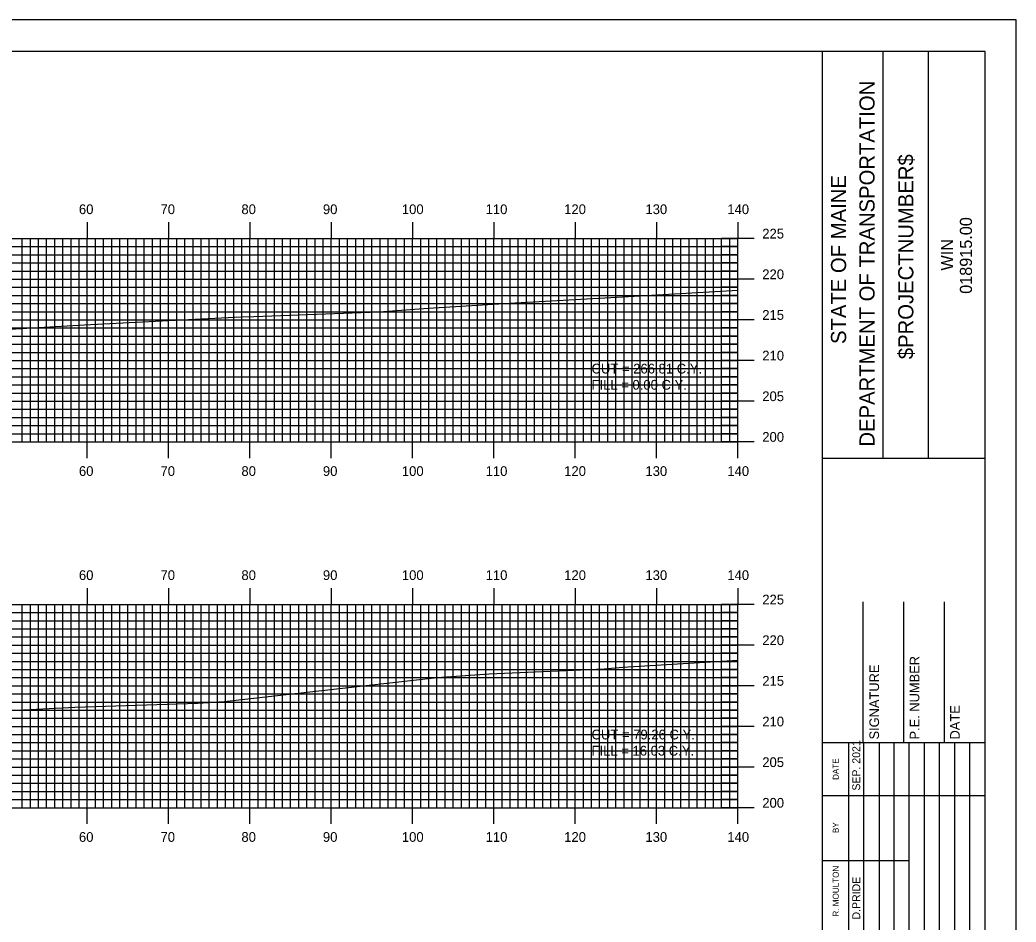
# Model space of a CAD drawing. Extents: x 853316 to 853659, y 364785 to 365005.
# Drawn here: x 853533.5 to 853656, y 364894.2 to 365005.1 of the extents above; entities that cross this region are included whole.
import ezdxf

# ---------------------------------------------------------------- set-up
doc = ezdxf.new("R2010")
doc.units = 0
for name, color, linetype in [('BORDER', 7, 'Continuous'), ('D_Text_Standard', 7, 'Continuous'), ('H_V ANNOTATION', 7, 'Continuous'), ('MAJOR', 7, 'Continuous'), ('MINOR', 7, 'Continuous'), ('PLOT BOUNDARY', 7, 'Continuous'), ('S_Roadway_Centerline', 7, 'Continuous')]:
    doc.layers.add(name, color=color, linetype=linetype)

msp = doc.modelspace()

# ---------------------------------------------------------------- linework, layer by layer
at = {"layer": 'BORDER'}
for p, q in [((853632.16, 364791.23), (853632.16, 365001.23)), ((853639.61, 364951.23), (853639.61, 365001.23)), ((853645.2, 364951.23), (853645.2, 365001.23)), ((853632.16, 364951.22), (853652.16, 364951.22)), ((853637.16, 364916.24), (853637.16, 364933.53)), ((853642.16, 364916.24), (853642.16, 364933.53)), ((853647.16, 364916.24), (853647.16, 364933.53)), ((853632.16, 364916.24), (853652.16, 364916.24))]:
    msp.add_line(p, q, dxfattribs=at)
msp.add_lwpolyline([(853332.16, 364791.23), (853652.16, 364791.23), (853652.16, 365001.23), (853332.16, 365001.23)], close=True, dxfattribs=at)
for points in [[(853635.39, 364909.74), (853635.39, 364916.24)], [(853637.25, 364881.24), (853637.25, 364916.24)], [(853639.12, 364916.24), (853639.12, 364881.24)], [(853640.98, 364881.24), (853640.98, 364916.24)], [(853642.84, 364881.24), (853642.84, 364916.24)], [(853644.71, 364881.24), (853644.71, 364916.24)], [(853646.57, 364881.24), (853646.57, 364916.24)], [(853648.43, 364881.24), (853648.43, 364916.24)], [(853650.3, 364881.24), (853650.3, 364916.24)], [(853635.39, 364881.24), (853635.39, 364914.83)], [(853632.16, 364909.74), (853652.16, 364909.74)], [(853632.16, 364901.74), (853635.39, 364901.74)], [(853635.39, 364901.74), (853642.84, 364901.74)]]:
    msp.add_lwpolyline(points, dxfattribs=at)
at = {"layer": 'MAJOR'}
for p, q in [((853541.76, 364980.24), (853541.76, 364978.23)), ((853551.76, 364980.24), (853551.76, 364978.23)), ((853561.76, 364980.24), (853561.76, 364978.23)), ((853571.76, 364980.24), (853571.76, 364978.23)), ((853581.76, 364980.24), (853581.76, 364978.23)), ((853591.76, 364980.24), (853591.76, 364978.23)), ((853601.76, 364980.24), (853601.76, 364978.23)), ((853611.76, 364980.24), (853611.76, 364978.23)), ((853621.76, 364980.24), (853621.76, 364978.23)), ((853341.76, 364978.23), (853621.76, 364978.23)), ((853341.76, 364978.23), (853621.76, 364978.23)), ((853541.76, 364953.23), (853541.76, 364978.23)), ((853551.76, 364953.23), (853551.76, 364978.23)), ((853561.76, 364953.23), (853561.76, 364978.23)), ((853571.76, 364953.23), (853571.76, 364978.23)), ((853581.76, 364953.23), (853581.76, 364978.23)), ((853591.76, 364953.23), (853591.76, 364978.23)), ((853601.76, 364953.23), (853601.76, 364978.23)), ((853611.76, 364953.23), (853611.76, 364978.23)), ((853623.76, 364978.23), (853619.75, 364978.23)), ((853621.76, 364953.23), (853621.76, 364978.23)), ((853621.76, 364953.23), (853621.76, 364978.23)), ((853341.76, 364973.23), (853621.76, 364973.23)), ((853623.76, 364973.23), (853619.75, 364973.23)), ((853341.76, 364968.23), (853621.76, 364968.23)), ((853623.76, 364968.23), (853619.75, 364968.23)), ((853341.76, 364963.23), (853621.76, 364963.23)), ((853623.76, 364963.23), (853619.75, 364963.23)), ((853341.76, 364958.23), (853621.76, 364958.23)), ((853623.76, 364958.23), (853619.75, 364958.23)), ((853341.76, 364953.23), (853621.76, 364953.23)), ((853341.76, 364953.23), (853621.76, 364953.23)), ((853541.76, 364951.23), (853541.76, 364953.23)), ((853551.76, 364951.23), (853551.76, 364953.23)), ((853561.76, 364951.23), (853561.76, 364953.23)), ((853571.76, 364951.23), (853571.76, 364953.23)), ((853581.76, 364951.23), (853581.76, 364953.23)), ((853591.76, 364951.23), (853591.76, 364953.23)), ((853601.76, 364951.23), (853601.76, 364953.23)), ((853611.76, 364951.23), (853611.76, 364953.23)), ((853623.76, 364953.23), (853619.75, 364953.23)), ((853621.76, 364951.23), (853621.76, 364953.23)), ((853541.76, 364935.24), (853541.76, 364933.23)), ((853551.76, 364935.24), (853551.76, 364933.23)), ((853561.76, 364935.24), (853561.76, 364933.23)), ((853571.76, 364935.24), (853571.76, 364933.23)), ((853581.76, 364935.24), (853581.76, 364933.23)), ((853591.76, 364935.24), (853591.76, 364933.23)), ((853601.76, 364935.24), (853601.76, 364933.23)), ((853611.76, 364935.24), (853611.76, 364933.23)), ((853621.76, 364935.24), (853621.76, 364933.23)), ((853341.76, 364933.23), (853621.76, 364933.23)), ((853341.76, 364933.23), (853621.76, 364933.23)), ((853541.76, 364908.23), (853541.76, 364933.23)), ((853551.76, 364908.23), (853551.76, 364933.23)), ((853561.76, 364908.23), (853561.76, 364933.23)), ((853571.76, 364908.23), (853571.76, 364933.23)), ((853581.76, 364908.23), (853581.76, 364933.23)), ((853591.76, 364908.23), (853591.76, 364933.23)), ((853601.76, 364908.23), (853601.76, 364933.23)), ((853611.76, 364908.23), (853611.76, 364933.23)), ((853623.76, 364933.23), (853619.75, 364933.23)), ((853621.76, 364908.23), (853621.76, 364933.23)), ((853621.76, 364908.23), (853621.76, 364933.23)), ((853341.76, 364928.23), (853621.76, 364928.23)), ((853623.76, 364928.23), (853619.75, 364928.23)), ((853341.76, 364923.23), (853621.76, 364923.23)), ((853623.76, 364923.23), (853619.75, 364923.23)), ((853341.76, 364918.23), (853621.76, 364918.23)), ((853623.76, 364918.23), (853619.75, 364918.23)), ((853341.76, 364913.23), (853621.76, 364913.23)), ((853623.76, 364913.23), (853619.75, 364913.23)), ((853341.76, 364908.23), (853621.76, 364908.23)), ((853341.76, 364908.23), (853621.76, 364908.23)), ((853541.76, 364906.23), (853541.76, 364908.23)), ((853551.76, 364906.23), (853551.76, 364908.23)), ((853561.76, 364906.23), (853561.76, 364908.23)), ((853571.76, 364906.23), (853571.76, 364908.23)), ((853581.76, 364906.23), (853581.76, 364908.23)), ((853591.76, 364906.23), (853591.76, 364908.23)), ((853601.76, 364906.23), (853601.76, 364908.23)), ((853611.76, 364906.23), (853611.76, 364908.23)), ((853623.76, 364908.23), (853619.75, 364908.23)), ((853621.76, 364906.23), (853621.76, 364908.23))]:
    msp.add_line(p, q, dxfattribs=at)
at = {"layer": 'MINOR'}
for p, q in [((853533.76, 364953.23), (853533.76, 364978.23)), ((853534.76, 364953.23), (853534.76, 364978.23)), ((853535.76, 364953.23), (853535.76, 364978.23)), ((853536.76, 364953.23), (853536.76, 364978.23)), ((853537.76, 364953.23), (853537.76, 364978.23)), ((853538.76, 364953.23), (853538.76, 364978.23)), ((853539.76, 364953.23), (853539.76, 364978.23)), ((853540.76, 364953.23), (853540.76, 364978.23)), ((853542.76, 364953.23), (853542.76, 364978.23)), ((853543.76, 364953.23), (853543.76, 364978.23)), ((853544.76, 364953.23), (853544.76, 364978.23)), ((853545.76, 364953.23), (853545.76, 364978.23)), ((853546.76, 364953.23), (853546.76, 364978.23)), ((853547.76, 364953.23), (853547.76, 364978.23)), ((853548.76, 364953.23), (853548.76, 364978.23)), ((853549.76, 364953.23), (853549.76, 364978.23)), ((853550.76, 364953.23), (853550.76, 364978.23)), ((853552.76, 364953.23), (853552.76, 364978.23)), ((853553.76, 364953.23), (853553.76, 364978.23)), ((853554.76, 364953.23), (853554.76, 364978.23)), ((853555.76, 364953.23), (853555.76, 364978.23)), ((853556.76, 364953.23), (853556.76, 364978.23)), ((853557.76, 364953.23), (853557.76, 364978.23)), ((853558.76, 364953.23), (853558.76, 364978.23)), ((853559.76, 364953.23), (853559.76, 364978.23)), ((853560.76, 364953.23), (853560.76, 364978.23)), ((853562.76, 364953.23), (853562.76, 364978.23)), ((853563.76, 364953.23), (853563.76, 364978.23)), ((853564.76, 364953.23), (853564.76, 364978.23)), ((853565.76, 364953.23), (853565.76, 364978.23)), ((853566.76, 364953.23), (853566.76, 364978.23)), ((853567.76, 364953.23), (853567.76, 364978.23)), ((853568.76, 364953.23), (853568.76, 364978.23)), ((853569.76, 364953.23), (853569.76, 364978.23)), ((853570.76, 364953.23), (853570.76, 364978.23)), ((853572.76, 364953.23), (853572.76, 364978.23)), ((853573.76, 364953.23), (853573.76, 364978.23)), ((853574.76, 364953.23), (853574.76, 364978.23)), ((853575.76, 364953.23), (853575.76, 364978.23)), ((853576.76, 364953.23), (853576.76, 364978.23)), ((853577.76, 364953.23), (853577.76, 364978.23)), ((853578.76, 364953.23), (853578.76, 364978.23)), ((853579.76, 364953.23), (853579.76, 364978.23)), ((853580.76, 364953.23), (853580.76, 364978.23)), ((853582.76, 364953.23), (853582.76, 364978.23)), ((853583.76, 364953.23), (853583.76, 364978.23)), ((853584.76, 364953.23), (853584.76, 364978.23)), ((853585.76, 364953.23), (853585.76, 364978.23)), ((853586.76, 364953.23), (853586.76, 364978.23)), ((853587.76, 364953.23), (853587.76, 364978.23)), ((853588.76, 364953.23), (853588.76, 364978.23)), ((853589.76, 364953.23), (853589.76, 364978.23)), ((853590.76, 364953.23), (853590.76, 364978.23)), ((853592.76, 364953.23), (853592.76, 364978.23)), ((853593.76, 364953.23), (853593.76, 364978.23)), ((853594.76, 364953.23), (853594.76, 364978.23)), ((853595.76, 364953.23), (853595.76, 364978.23)), ((853596.76, 364953.23), (853596.76, 364978.23)), ((853597.76, 364953.23), (853597.76, 364978.23)), ((853598.76, 364953.23), (853598.76, 364978.23)), ((853599.76, 364953.23), (853599.76, 364978.23)), ((853600.76, 364953.23), (853600.76, 364978.23)), ((853602.76, 364953.23), (853602.76, 364978.23)), ((853603.76, 364953.23), (853603.76, 364978.23)), ((853604.76, 364953.23), (853604.76, 364978.23)), ((853605.76, 364953.23), (853605.76, 364978.23)), ((853606.76, 364953.23), (853606.76, 364978.23)), ((853607.76, 364953.23), (853607.76, 364978.23)), ((853608.76, 364953.23), (853608.76, 364978.23)), ((853609.76, 364953.23), (853609.76, 364978.23)), ((853610.76, 364953.23), (853610.76, 364978.23)), ((853612.76, 364953.23), (853612.76, 364978.23)), ((853613.76, 364953.23), (853613.76, 364978.23)), ((853614.76, 364953.23), (853614.76, 364978.23)), ((853615.76, 364953.23), (853615.76, 364978.23)), ((853616.76, 364953.23), (853616.76, 364978.23)), ((853617.76, 364953.23), (853617.76, 364978.23)), ((853618.76, 364953.23), (853618.76, 364978.23)), ((853619.76, 364953.23), (853619.76, 364978.23)), ((853620.76, 364953.23), (853620.76, 364978.23)), ((853341.76, 364977.23), (853621.76, 364977.23)), ((853621.76, 364977.23), (853619.75, 364977.23)), ((853341.76, 364976.23), (853621.76, 364976.23)), ((853621.76, 364976.23), (853619.75, 364976.23)), ((853341.76, 364975.23), (853621.76, 364975.23)), ((853621.76, 364975.23), (853619.75, 364975.23)), ((853341.76, 364974.23), (853621.76, 364974.23)), ((853621.76, 364974.23), (853619.75, 364974.23)), ((853341.76, 364972.23), (853621.76, 364972.23)), ((853621.76, 364972.23), (853619.75, 364972.23)), ((853341.76, 364971.23), (853621.76, 364971.23)), ((853621.76, 364971.23), (853619.75, 364971.23)), ((853341.76, 364970.23), (853621.76, 364970.23)), ((853621.76, 364970.23), (853619.75, 364970.23)), ((853341.76, 364969.23), (853621.76, 364969.23)), ((853621.76, 364969.23), (853619.75, 364969.23)), ((853341.76, 364967.23), (853621.76, 364967.23)), ((853621.76, 364967.23), (853619.75, 364967.23)), ((853341.76, 364966.23), (853621.76, 364966.23)), ((853621.76, 364966.23), (853619.75, 364966.23)), ((853341.76, 364965.23), (853621.76, 364965.23)), ((853621.76, 364965.23), (853619.75, 364965.23)), ((853341.76, 364964.23), (853621.76, 364964.23)), ((853621.76, 364964.23), (853619.75, 364964.23)), ((853341.76, 364962.23), (853621.76, 364962.23)), ((853621.76, 364962.23), (853619.75, 364962.23)), ((853341.76, 364961.23), (853621.76, 364961.23)), ((853621.76, 364961.23), (853619.75, 364961.23)), ((853341.76, 364960.23), (853621.76, 364960.23)), ((853621.76, 364960.23), (853619.75, 364960.23)), ((853341.76, 364959.23), (853621.76, 364959.23)), ((853621.76, 364959.23), (853619.75, 364959.23)), ((853341.76, 364957.23), (853621.76, 364957.23)), ((853341.76, 364956.23), (853621.76, 364956.23)), ((853621.76, 364957.23), (853619.75, 364957.23)), ((853621.76, 364956.23), (853619.75, 364956.23)), ((853341.76, 364955.23), (853621.76, 364955.23)), ((853621.76, 364955.23), (853619.75, 364955.23)), ((853341.76, 364954.23), (853621.76, 364954.23)), ((853621.76, 364954.23), (853619.75, 364954.23)), ((853533.76, 364908.23), (853533.76, 364933.23)), ((853534.76, 364908.23), (853534.76, 364933.23)), ((853535.76, 364908.23), (853535.76, 364933.23)), ((853536.76, 364908.23), (853536.76, 364933.23)), ((853537.76, 364908.23), (853537.76, 364933.23)), ((853538.76, 364908.23), (853538.76, 364933.23)), ((853539.76, 364908.23), (853539.76, 364933.23)), ((853540.76, 364908.23), (853540.76, 364933.23)), ((853542.76, 364908.23), (853542.76, 364933.23)), ((853543.76, 364908.23), (853543.76, 364933.23)), ((853544.76, 364908.23), (853544.76, 364933.23)), ((853545.76, 364908.23), (853545.76, 364933.23)), ((853546.76, 364908.23), (853546.76, 364933.23)), ((853547.76, 364908.23), (853547.76, 364933.23)), ((853548.76, 364908.23), (853548.76, 364933.23)), ((853549.76, 364908.23), (853549.76, 364933.23)), ((853550.76, 364908.23), (853550.76, 364933.23)), ((853552.76, 364908.23), (853552.76, 364933.23)), ((853553.76, 364908.23), (853553.76, 364933.23)), ((853554.76, 364908.23), (853554.76, 364933.23)), ((853555.76, 364908.23), (853555.76, 364933.23)), ((853556.76, 364908.23), (853556.76, 364933.23)), ((853557.76, 364908.23), (853557.76, 364933.23)), ((853558.76, 364908.23), (853558.76, 364933.23)), ((853559.76, 364908.23), (853559.76, 364933.23)), ((853560.76, 364908.23), (853560.76, 364933.23)), ((853562.76, 364908.23), (853562.76, 364933.23)), ((853563.76, 364908.23), (853563.76, 364933.23)), ((853564.76, 364908.23), (853564.76, 364933.23)), ((853565.76, 364908.23), (853565.76, 364933.23)), ((853566.76, 364908.23), (853566.76, 364933.23)), ((853567.76, 364908.23), (853567.76, 364933.23)), ((853568.76, 364908.23), (853568.76, 364933.23)), ((853569.76, 364908.23), (853569.76, 364933.23)), ((853570.76, 364908.23), (853570.76, 364933.23)), ((853572.76, 364908.23), (853572.76, 364933.23)), ((853573.76, 364908.23), (853573.76, 364933.23)), ((853574.76, 364908.23), (853574.76, 364933.23)), ((853575.76, 364908.23), (853575.76, 364933.23)), ((853576.76, 364908.23), (853576.76, 364933.23)), ((853577.76, 364908.23), (853577.76, 364933.23)), ((853578.76, 364908.23), (853578.76, 364933.23)), ((853579.76, 364908.23), (853579.76, 364933.23)), ((853580.76, 364908.23), (853580.76, 364933.23)), ((853582.76, 364908.23), (853582.76, 364933.23)), ((853583.76, 364908.23), (853583.76, 364933.23)), ((853584.76, 364908.23), (853584.76, 364933.23)), ((853585.76, 364908.23), (853585.76, 364933.23)), ((853586.76, 364908.23), (853586.76, 364933.23)), ((853587.76, 364908.23), (853587.76, 364933.23)), ((853588.76, 364908.23), (853588.76, 364933.23)), ((853589.76, 364908.23), (853589.76, 364933.23)), ((853590.76, 364908.23), (853590.76, 364933.23)), ((853592.76, 364908.23), (853592.76, 364933.23)), ((853593.76, 364908.23), (853593.76, 364933.23)), ((853594.76, 364908.23), (853594.76, 364933.23)), ((853595.76, 364908.23), (853595.76, 364933.23)), ((853596.76, 364908.23), (853596.76, 364933.23)), ((853597.76, 364908.23), (853597.76, 364933.23)), ((853598.76, 364908.23), (853598.76, 364933.23)), ((853599.76, 364908.23), (853599.76, 364933.23)), ((853600.76, 364908.23), (853600.76, 364933.23)), ((853602.76, 364908.23), (853602.76, 364933.23)), ((853603.76, 364908.23), (853603.76, 364933.23)), ((853604.76, 364908.23), (853604.76, 364933.23)), ((853605.76, 364908.23), (853605.76, 364933.23)), ((853606.76, 364908.23), (853606.76, 364933.23)), ((853607.76, 364908.23), (853607.76, 364933.23)), ((853608.76, 364908.23), (853608.76, 364933.23)), ((853609.76, 364908.23), (853609.76, 364933.23)), ((853610.76, 364908.23), (853610.76, 364933.23)), ((853612.76, 364908.23), (853612.76, 364933.23)), ((853613.76, 364908.23), (853613.76, 364933.23)), ((853614.76, 364908.23), (853614.76, 364933.23)), ((853615.76, 364908.23), (853615.76, 364933.23)), ((853616.76, 364908.23), (853616.76, 364933.23)), ((853617.76, 364908.23), (853617.76, 364933.23)), ((853618.76, 364908.23), (853618.76, 364933.23)), ((853619.76, 364908.23), (853619.76, 364933.23)), ((853620.76, 364908.23), (853620.76, 364933.23)), ((853341.76, 364932.23), (853621.76, 364932.23)), ((853621.76, 364932.23), (853619.75, 364932.23)), ((853341.76, 364931.23), (853621.76, 364931.23)), ((853621.76, 364931.23), (853619.75, 364931.23)), ((853341.76, 364930.23), (853621.76, 364930.23)), ((853341.76, 364929.23), (853621.76, 364929.23)), ((853621.76, 364930.23), (853619.75, 364930.23)), ((853621.76, 364929.23), (853619.75, 364929.23)), ((853341.76, 364927.23), (853621.76, 364927.23)), ((853621.76, 364927.23), (853619.75, 364927.23)), ((853341.76, 364926.23), (853621.76, 364926.23)), ((853621.76, 364926.23), (853619.75, 364926.23)), ((853341.76, 364925.23), (853621.76, 364925.23)), ((853621.76, 364925.23), (853619.75, 364925.23)), ((853341.76, 364924.23), (853621.76, 364924.23)), ((853621.76, 364924.23), (853619.75, 364924.23)), ((853341.76, 364922.23), (853621.76, 364922.23)), ((853621.76, 364922.23), (853619.75, 364922.23)), ((853341.76, 364921.23), (853621.76, 364921.23)), ((853621.76, 364921.23), (853619.75, 364921.23)), ((853341.76, 364920.23), (853621.76, 364920.23)), ((853621.76, 364920.23), (853619.75, 364920.23)), ((853341.76, 364919.23), (853621.76, 364919.23)), ((853621.76, 364919.23), (853619.75, 364919.23)), ((853341.76, 364917.23), (853621.76, 364917.23)), ((853621.76, 364917.23), (853619.75, 364917.23)), ((853341.76, 364916.23), (853621.76, 364916.23)), ((853621.76, 364916.23), (853619.75, 364916.23)), ((853341.76, 364915.23), (853621.76, 364915.23)), ((853621.76, 364915.23), (853619.75, 364915.23)), ((853341.76, 364914.23), (853621.76, 364914.23)), ((853621.76, 364914.23), (853619.75, 364914.23)), ((853341.76, 364912.23), (853621.76, 364912.23)), ((853621.76, 364912.23), (853619.75, 364912.23)), ((853341.76, 364911.23), (853621.76, 364911.23)), ((853621.76, 364911.23), (853619.75, 364911.23)), ((853341.76, 364910.23), (853621.76, 364910.23)), ((853621.76, 364910.23), (853619.75, 364910.23)), ((853341.76, 364909.23), (853621.76, 364909.23)), ((853621.76, 364909.23), (853619.75, 364909.23))]:
    msp.add_line(p, q, dxfattribs=at)
at = {"layer": 'PLOT BOUNDARY'}
msp.add_lwpolyline([(853315.97, 364785.11), (853655.97, 364785.11), (853655.97, 365005.11), (853315.97, 365005.11)], close=True, dxfattribs=at)
at = {"layer": 'S_Roadway_Centerline'}
for points in [[(853341.76, 364960.71), (853345.93, 364960.83), (853353.35, 364961.01), (853361.55, 364961.33), (853402.27, 364962.38), (853412.31, 364962.57), (853439.83, 364963.53), (853463.65, 364964.4), (853479.24, 364964.85), (853485.19, 364965.12), (853498.57, 364965.58), (853509.74, 364965.76), (853537.83, 364967.42), (853541.41, 364967.63), (853545.3, 364967.83), (853560.67, 364968.6), (853562.25, 364968.66), (853577.65, 364969.22), (853583.69, 364969.65), (853594.37, 364970.31), (853607.63, 364971.07), (853621.76, 364971.89)], [(853341.76, 364914.32), (853347.1, 364914.42), (853353.88, 364914.55), (853369.34, 364915.29), (853370.22, 364915.33), (853385.95, 364915.91), (853387.75, 364916), (853390.71, 364916.13), (853393.68, 364916.23), (853430.05, 364916.84), (853444.48, 364917.05), (853452.3, 364917.5), (853506.17, 364918.85), (853506.72, 364918.86), (853507.22, 364918.88), (853507.88, 364918.91), (853540.24, 364920.6), (853555.34, 364921.1), (853558.6, 364921.29), (853584.78, 364924.26), (853591.18, 364924.71), (853605.32, 364925.33), (853607.63, 364925.51), (853621.76, 364926.36)]]:
    msp.add_lwpolyline(points, dxfattribs=at)

# ---------------------------------------------------------------- texts
at = {"layer": 'BORDER'}
for s, height, p in [('DEPARTMENT OF TRANSPORTATION', 1.8635, (853638.57, 364952.64)), ('$PROJECTNUMBER$', 1.8635, (853643.34, 364963.39)), ('STATE OF MAINE', 1.8635, (853635.07, 364965.26)), ('018915.00', 1.491, (853650.55, 364971.43)), ('WIN', 1.491, (853648.23, 364974.29)), ('P.E. NUMBER', 1.1811, (853644.08, 364916.62)), ('SIGNATURE', 1.181, (853639.12, 364916.62)), ('DATE', 1.181, (853649.04, 364916.62)), ('SEP. 2021', 0.969, (853636.8, 364910.33)), ('DATE', 0.743, (853634.17, 364911.65)), ('BY', 0.743, (853634.17, 364905.11)), ('R. MOULTON', 0.745, (853634.17, 364894.84)), ('D.PRIDE', 0.969, (853636.8, 364894.48))]:
    msp.add_text(s, height=height, rotation=90, dxfattribs=at).set_placement(p)
at = {"layer": 'D_Text_Standard'}
for s, p in [('CUT = 266.81 C.Y.', (853603.76, 364961.63)), ('FILL = 0.00 C.Y.', (853603.76, 364959.64)), ('CUT = 79.26 C.Y.', (853603.76, 364916.63)), ('FILL = 16.03 C.Y.', (853603.76, 364914.64))]:
    msp.add_text(s, height=1.2, dxfattribs=at).set_placement(p)
at = {"layer": 'H_V ANNOTATION'}
for s, p in [('60', (853540.73, 364981.23)), ('70', (853550.76, 364981.23)), ('80', (853560.71, 364981.23)), ('90', (853570.73, 364981.23)), ('100', (853580.44, 364981.23)), ('110', (853590.74, 364981.23)), ('120', (853600.4, 364981.23)), ('130', (853610.39, 364981.23)), ('140', (853620.46, 364981.23)), ('225', (853624.76, 364978.23)), ('220', (853624.76, 364973.23)), ('215', (853624.76, 364968.23)), ('210', (853624.76, 364963.23)), ('205', (853624.76, 364958.23)), ('200', (853624.76, 364953.23)), ('60', (853540.73, 364949.03)), ('70', (853550.76, 364949.03)), ('80', (853560.71, 364949.03)), ('90', (853570.73, 364949.03)), ('100', (853580.44, 364949.03)), ('110', (853590.74, 364949.03)), ('120', (853600.4, 364949.03)), ('130', (853610.39, 364949.03)), ('140', (853620.46, 364949.03)), ('60', (853540.73, 364936.23)), ('70', (853550.76, 364936.23)), ('80', (853560.71, 364936.23)), ('90', (853570.73, 364936.23)), ('100', (853580.44, 364936.23)), ('110', (853590.74, 364936.23)), ('120', (853600.4, 364936.23)), ('130', (853610.39, 364936.23)), ('140', (853620.46, 364936.23)), ('225', (853624.76, 364933.23)), ('220', (853624.76, 364928.23)), ('215', (853624.76, 364923.23)), ('210', (853624.76, 364918.23)), ('205', (853624.76, 364913.23)), ('200', (853624.76, 364908.23)), ('60', (853540.73, 364904.03)), ('70', (853550.76, 364904.03)), ('80', (853560.71, 364904.03)), ('90', (853570.73, 364904.03)), ('100', (853580.44, 364904.03)), ('110', (853590.74, 364904.03)), ('120', (853600.4, 364904.03)), ('130', (853610.39, 364904.03)), ('140', (853620.46, 364904.03))]:
    msp.add_text(s, height=1.2, dxfattribs=at).set_placement(p)

doc.saveas('drawing.dxf')
